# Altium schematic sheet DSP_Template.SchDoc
size A4
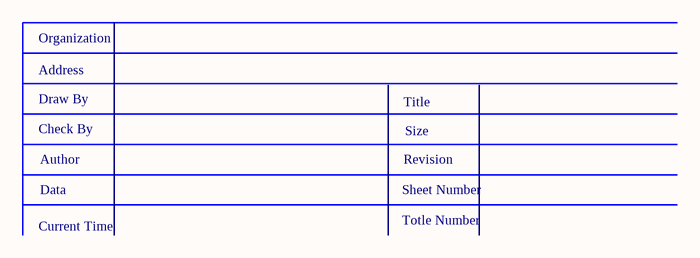
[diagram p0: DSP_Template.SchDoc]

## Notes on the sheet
- Organization
- Draw By
- Check By
- Address
- Title
- Size
- Data
- Author
- Sheet Number
- Revision
- Current Time
- Totle Number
